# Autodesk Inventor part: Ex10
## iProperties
Author: Administrator
Created: 2001-01
Part Number: Ex10
Material: Aluminum
Document SubType Name: Sheet Metal
Designer: Administrator
Control State: 0
Master: False
Checked Out: False
PropertySet Name: Design Tracking Control
Shininess: 25.0
PropertySet Name: _Private Model Information
Density: 0.0
Volumn: 0.0
Area: 0.0
PropertySet Name: Model Information
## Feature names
1. Corner Round1
2. Corner Round2
3. Cut1
4. Hole1
5. Cut2
6. Cut3
7. Plate1
8. Plate2
9. Bend1
10. Plate3
11. Bend2
